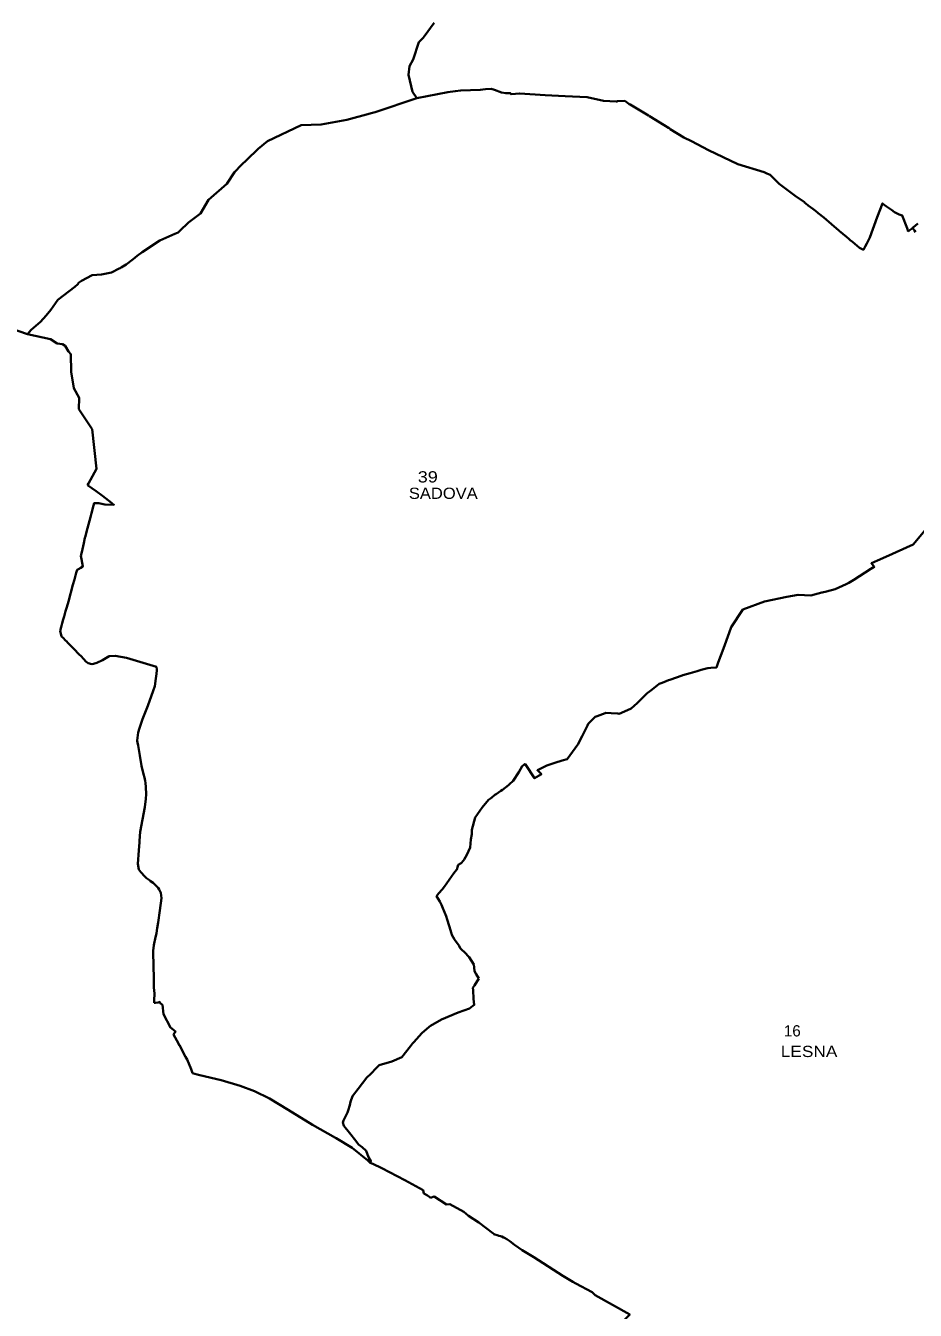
# Model space of a CAD drawing. Extents: x -610940 to -588976, y -1170376 to -1149800.
# Drawn here: x -598311 to -596331, y -1157762 to -1154902 of the extents above; entities that cross this region are included whole.
import ezdxf

# ---------------------------------------------------------------- set-up
doc = ezdxf.new("R2010")
doc.units = 0
doc.header["$LTSCALE"] = 10
doc.layers.add('54', color=7, linetype='Continuous', lineweight=35)
doc.layers.add('55', color=7, linetype='Continuous')
doc.layers.add('56', color=7, linetype='Continuous')

msp = doc.modelspace()

# ---------------------------------------------------------------- linework, layer by layer
at = {"layer": '54'}
for p, q in [((-597440.72, -1155063.97), (-597371.53, -1155050.6)), ((-598171.36, -1155921.75), (-598173.66, -1155924.96)), ((-598173.66, -1155924.96), (-598154.78, -1155938.64)), ((-598179.32, -1156041.24), (-598179.57, -1156042.23)), ((-598190.16, -1156110.24), (-598192.56, -1156111.77)), ((-598228.25, -1156265.11), (-598227.41, -1156265.97)), ((-598223.4, -1156270.12), (-598227.41, -1156265.97)), ((-598020.33, -1156345.49), (-598019.46, -1156337.07)), ((-598019.28, -1156335.32), (-598019.46, -1156337.07)), ((-598027.48, -1156383.15), (-598039.51, -1156416.77)), ((-598023.68, -1156372.54), (-598027.48, -1156383.15)), ((-598048.8, -1156568.82), (-598047.23, -1156576.36)), ((-598058.11, -1156720), (-598059.82, -1156738.65)), ((-598042.46, -1156799.86), (-598035.88, -1156804.79)), ((-598016.38, -1156821.88), (-598014.41, -1156825.37)), ((-598010.28, -1156832.71), (-598014.41, -1156825.37)), ((-598026.34, -1157039.35), (-598026.19, -1157024.28)), ((-598026.34, -1157039.35), (-598025.99, -1157043.8)), ((-598026.16, -1157021.34), (-598026.19, -1157024.28)), ((-598024.97, -1157056.82), (-598025.99, -1157043.8)), ((-598025.16, -1157077.69), (-598025.12, -1157072.76)), ((-598024.97, -1157056.82), (-598025.12, -1157072.76)), ((-597955.88, -1157197.66), (-597952.02, -1157204.06)), ((-597423.33, -1157502.84), (-597417.19, -1157506.85)), ((-597411.69, -1157510.45), (-597417.19, -1157506.85)), ((-597411.69, -1157510.45), (-597410.12, -1157511.52)), ((-597086.81, -1157702.7), (-597050.48, -1157721.63))]:
    msp.add_line(p, q, dxfattribs=at)
for points in [[(-597401.83, -1154896.17), (-597424.1, -1154926.78), (-597426.89, -1154929.69), (-597436.01, -1154939.33), (-597449.07, -1154977.53), (-597456.93, -1154992.27), (-597459.41, -1155011.97), (-597450.5, -1155049.32), (-597440.72, -1155063.97), (-597533.72, -1155095.04), (-597542.11, -1155097.33), (-597544.35, -1155097.94), (-597596.39, -1155112.14), (-597653.4, -1155122.02), (-597698.51, -1155123.98), (-597773.13, -1155159.09), (-597794.22, -1155176.34), (-597819.24, -1155201.09), (-597830.73, -1155212.47), (-597846.64, -1155228.22), (-597863.65, -1155254.11), (-597904.42, -1155289.69), (-597922.1, -1155320.54), (-597949.06, -1155340.26), (-597968.47, -1155359.05), (-597971.99, -1155362.46), (-597979.59, -1155365.94), (-598012.46, -1155380.94), (-598052.04, -1155406.28)], [(-597371.53, -1155050.6), (-597355.16, -1155048.25), (-597343, -1155046.39), (-597299.36, -1155045.19), (-597287.82, -1155043.79), (-597275.51, -1155043.07), (-597268.03, -1155045.06), (-597252.48, -1155051.2), (-597242.66, -1155052.79), (-597232.7, -1155052.31), (-597230.76, -1155055.09), (-597211.43, -1155053.08), (-597155.04, -1155056.88), (-597110.81, -1155059.06), (-597061.76, -1155061.63), (-597025, -1155069.9), (-596996.7, -1155070.91), (-596995.41, -1155071.14), (-596993.78, -1155070.7), (-596977.72, -1155069.87), (-596974.52, -1155072.14), (-596972.81, -1155073.32), (-596967.74, -1155076.82), (-596965.66, -1155078.18), (-596924.69, -1155102.41), (-596922.75, -1155103.5), (-596890.24, -1155123.8), (-596880.65, -1155129.85), (-596880.53, -1155129.92), (-596877.58, -1155131.63), (-596876.69, -1155132.47), (-596845.95, -1155151.29), (-596829.5, -1155159.19), (-596791.52, -1155179.38), (-596726.34, -1155210.29), (-596667.74, -1155228.2), (-596661.6, -1155231.25), (-596654.44, -1155234.55), (-596648.89, -1155239.88), (-596635.64, -1155252.59)], [(-596635.64, -1155252.59), (-596633.78, -1155254.38), (-596598.54, -1155281.19), (-596577.84, -1155295.58), (-596576.96, -1155296.39), (-596574.65, -1155298.2), (-596569.2, -1155302.4), (-596559.11, -1155310.21), (-596553.38, -1155314.69), (-596547.66, -1155319.16), (-596547.18, -1155319.44), (-596534.84, -1155329.64), (-596517.8, -1155344.17), (-596501.51, -1155358.2), (-596500.75, -1155358.65), (-596500.5, -1155358.86), (-596484.51, -1155372.16), (-596482.84, -1155373.55), (-596480.59, -1155375.44), (-596475.66, -1155379.52), (-596470.94, -1155383.42), (-596455.05, -1155396.67), (-596453.53, -1155397.4), (-596446.56, -1155401.32), (-596445.5, -1155399.55), (-596442.76, -1155394.21), (-596439, -1155387), (-596432.41, -1155374), (-596415.6, -1155329), (-596404.13, -1155298.13), (-596403.45, -1155298.8), (-596394.92, -1155304.89), (-596384.38, -1155312.42), (-596377.66, -1155317.21), (-596373.24, -1155319.56), (-596367.2, -1155322.78), (-596360.28, -1155324.79), (-596359.96, -1155324.81), (-596349.45, -1155353.2), (-596346.92, -1155360.69)], [(-596346.92, -1155360.69), (-596344.38, -1155358.64), (-596338.26, -1155353.56), (-596336.97, -1155352.54)], [(-596330.74, -1155362.38), (-596333.08, -1155358.65), (-596336.97, -1155352.54), (-596331.48, -1155348), (-596325.07, -1155342.61)], [(-598052.04, -1155406.28), (-598063.29, -1155415.08), (-598072.17, -1155422.02), (-598087.86, -1155434.12), (-598099.2, -1155440.77), (-598100.98, -1155441.82), (-598103.12, -1155442.89), (-598120.21, -1155451.46), (-598142.79, -1155456.28), (-598163.45, -1155457.83), (-598187.27, -1155470.14), (-598193.5, -1155475.15), (-598193.56, -1155475.24), (-598195.64, -1155477.47), (-598201.69, -1155483.93), (-598240.02, -1155512.71), (-598255.13, -1155535.26), (-598265.83, -1155547.67), (-598278.75, -1155561.42), (-598299.25, -1155579.49), (-598307.63, -1155589.43)], [(-598346.06, -1155575.76), (-598307.63, -1155589.43), (-598255.8, -1155600.47), (-598241.68, -1155609.85), (-598229.1, -1155611.46), (-598223.83, -1155614.73), (-598215.93, -1155627.71), (-598211.26, -1155633.56), (-598210.38, -1155673.12), (-598203.86, -1155709.15), (-598192.44, -1155731.13)], [(-598192.44, -1155731.13), (-598193.08, -1155755.78), (-598163.43, -1155800.82), (-598153.75, -1155888.66), (-598171.36, -1155921.75)], [(-598154.78, -1155938.64), (-598140.38, -1155949.07), (-598120.71, -1155964.6), (-598119.09, -1155966), (-598114.93, -1155968.65), (-598135.32, -1155967.99), (-598145.58, -1155966.04), (-598148.61, -1155965.14), (-598153.86, -1155965.31)], [(-598160.25, -1155970.16), (-598165.02, -1155987.9), (-598167.34, -1155996.67), (-598169.44, -1156004.5), (-598173.83, -1156020.65), (-598179.32, -1156041.24)], [(-598153.86, -1155965.31), (-598158.99, -1155965.49), (-598160.25, -1155970.16)], [(-598179.57, -1156042.23), (-598181.95, -1156054.13), (-598186.28, -1156074.1)], [(-596415.21, -1156093.02), (-596396.32, -1156084.7), (-596335.77, -1156057.31), (-596305.22, -1156020.75)], [(-598186.28, -1156074.1), (-598188.43, -1156082.66), (-598187.26, -1156089.83), (-598183.9, -1156106.22), (-598190.16, -1156110.24)], [(-596950.46, -1156410.4), (-596938.52, -1156398.81), (-596928.04, -1156388.44), (-596925.49, -1156386.61), (-596917.16, -1156380.09), (-596901.31, -1156367.29), (-596896.86, -1156365.73), (-596891.19, -1156363.6), (-596880.61, -1156359.54), (-596877.14, -1156358.35), (-596849.89, -1156348.58), (-596848.2, -1156348.06), (-596832.54, -1156343.54), (-596816.91, -1156339), (-596807.92, -1156336.39), (-596798.86, -1156333.76), (-596796.36, -1156333.04), (-596792.67, -1156332.73), (-596785.83, -1156332.15), (-596773.77, -1156331.21), (-596769.84, -1156320.22), (-596757.96, -1156288.9), (-596745.28, -1156253.69), (-596740.74, -1156241.51), (-596714.84, -1156202.02), (-596666.57, -1156184.54), (-596616.8, -1156173.93), (-596591.81, -1156169.19), (-596563.45, -1156170.48), (-596539.47, -1156164.49), (-596538.7, -1156164.25), (-596528.49, -1156161.94), (-596509.13, -1156156.55), (-596484.81, -1156145.45), (-596478.8, -1156142.64), (-596467.9, -1156135.71), (-596429.83, -1156111.83), (-596422.56, -1156107.09), (-596428.66, -1156099.2), (-596415.21, -1156093.02)], [(-598192.56, -1156111.77), (-598196.92, -1156113.79), (-598198.79, -1156120.45), (-598202.79, -1156135.01), (-598206.19, -1156147.3), (-598216.41, -1156184.02), (-598220.09, -1156196.98), (-598222.56, -1156205.75), (-598225.87, -1156217.33), (-598227.76, -1156224.46), (-598230.02, -1156232.65)], [(-598234.63, -1156249.78), (-598232.3, -1156241.1), (-598230.02, -1156232.65)], [(-598234.63, -1156249.78), (-598231.47, -1156261.87), (-598228.25, -1156265.11)], [(-598218.91, -1156274.75), (-598219.3, -1156274.35), (-598223.4, -1156270.12)], [(-598218.91, -1156274.75), (-598211.71, -1156282.33), (-598202.95, -1156291.42), (-598193.67, -1156300.39), (-598191.41, -1156302.61), (-598188.68, -1156305.13), (-598181.68, -1156312.39), (-598177.73, -1156317.44), (-598172.35, -1156321.14)], [(-598172.35, -1156321.14), (-598164.33, -1156323.36), (-598160.59, -1156322.63), (-598152.84, -1156320.48), (-598140.48, -1156315.01), (-598125.93, -1156306.08), (-598112.07, -1156305.23), (-598087.16, -1156309.75), (-598020.4, -1156329.99), (-598019.28, -1156335.32)], [(-598020.33, -1156345.49), (-598021.5, -1156355.86), (-598023.68, -1156372.54)], [(-598039.51, -1156416.77), (-598051.66, -1156446.09), (-598057.92, -1156465.85), (-598060.66, -1156475.91), (-598062.9, -1156493.59), (-598062.88, -1156495.37), (-598062.75, -1156497.36), (-598062.73, -1156498.29), (-598060.73, -1156504.95), (-598057.55, -1156526.95), (-598053.38, -1156550.03), (-598048.8, -1156568.82)], [(-597311.02, -1156665.4), (-597295.53, -1156642.5), (-597281.22, -1156625.98), (-597277.03, -1156622.5), (-597274.05, -1156620.2), (-597266.85, -1156614.77), (-597264.2, -1156612.97), (-597253.41, -1156605.59), (-597250.09, -1156603.17), (-597243.43, -1156598.3), (-597236.25, -1156593.1), (-597234.23, -1156590.48), (-597226.28, -1156583.13), (-597213.8, -1156563.87), (-597206.02, -1156550.78), (-597199.82, -1156545.58), (-597198.48, -1156547.37), (-597178.69, -1156577.68), (-597163.37, -1156568.59), (-597172.27, -1156559.84), (-597151.52, -1156549.5), (-597133.23, -1156543.68), (-597116.88, -1156538.52), (-597106.24, -1156535.07), (-597081.99, -1156502.85), (-597072.82, -1156484.31), (-597066.24, -1156470.93), (-597061.06, -1156460.37), (-597059.21, -1156456.68), (-597051.11, -1156448.57), (-597043.69, -1156441.16), (-597039.43, -1156439.62), (-597021.67, -1156433.01), (-597020.09, -1156432.39), (-597008.17, -1156433.06), (-596993.29, -1156433.87), (-596990.49, -1156433.96), (-596978.67, -1156429.13), (-596963.23, -1156422.69), (-596950.46, -1156410.4)], [(-598044.8, -1156587.68), (-598043.72, -1156597.22), (-598042.83, -1156613.03), (-598043.6, -1156623.29), (-598045.96, -1156641.72), (-598051.57, -1156669.64), (-598056.28, -1156696.93), (-598058.01, -1156717.13), (-598058.11, -1156720)], [(-598047.23, -1156576.36), (-598045.24, -1156583.54), (-598044.8, -1156587.68)], [(-597302.79, -1157023.53), (-597308.88, -1157013.74), (-597309.54, -1157012.92), (-597312.2, -1157006.69), (-597314.07, -1156992.58), (-597324.48, -1156975.83), (-597327.74, -1156972.29), (-597331.17, -1156968.38), (-597344.13, -1156956.18), (-597346.6, -1156950.83), (-597356.55, -1156936.27), (-597362.5, -1156926.59), (-597363.43, -1156923.54), (-597368.79, -1156906.07), (-597373.1, -1156892.2), (-597375.73, -1156884.91), (-597382.44, -1156866.95), (-597385.39, -1156859.5), (-597389.55, -1156852.36), (-597396.58, -1156840.22), (-597391.34, -1156833.44), (-597384.25, -1156825.08), (-597379.06, -1156818.63), (-597358.08, -1156789.23), (-597355.49, -1156785.49), (-597355.32, -1156785.24), (-597352.02, -1156781.53), (-597351.82, -1156781.3), (-597350.29, -1156775.28), (-597348.91, -1156770.53), (-597348.59, -1156770.35), (-597341.7, -1156766.38), (-597336.51, -1156760.44), (-597335.33, -1156758.86), (-597329.07, -1156748.15), (-597322.26, -1156732.16), (-597320.34, -1156713.9), (-597318.55, -1156702.04), (-597318.1, -1156692.44), (-597311.02, -1156665.4)], [(-598059.82, -1156738.65), (-598061.89, -1156768.06), (-598059.45, -1156781.06), (-598055.05, -1156786.59)], [(-598055.05, -1156786.59), (-598046.52, -1156796.73), (-598042.46, -1156799.86)], [(-598035.88, -1156804.79), (-598033.23, -1156806.59), (-598027.67, -1156810.79)], [(-598027.67, -1156810.79), (-598025.78, -1156812.16), (-598016.38, -1156821.88)], [(-598010.28, -1156832.71), (-598009.23, -1156844.81), (-598012.79, -1156871.78), (-598016.53, -1156898.78), (-598018.68, -1156911.18), (-598020.08, -1156922.81), (-598023.02, -1156935.03), (-598025.57, -1156945.43), (-598026.1, -1156948.87)], [(-598026.1, -1156948.87), (-598027.82, -1156961.98), (-598026.96, -1156998.47), (-598026.14, -1157019.41), (-598026.16, -1157021.34)], [(-597544.31, -1157433.57), (-597542.96, -1157430.01), (-597548.07, -1157421.21), (-597553.76, -1157407.04), (-597562.3, -1157398.54), (-597570.75, -1157392.99), (-597576.34, -1157384.93), (-597590.69, -1157366.7), (-597602.93, -1157351.19), (-597605.17, -1157343.85), (-597604.15, -1157339.57), (-597595.06, -1157321.64), (-597593.82, -1157316.93), (-597590.08, -1157305.41), (-597588.1, -1157298.06), (-597584.08, -1157285.18), (-597571.52, -1157269.08), (-597551.93, -1157244.09), (-597544.12, -1157236.18), (-597529.96, -1157221.82), (-597524.23, -1157216.22), (-597496.46, -1157207.92), (-597473.74, -1157198.26), (-597454.86, -1157173.89), (-597449.96, -1157168.2), (-597447.21, -1157165), (-597429.35, -1157145.45), (-597413.22, -1157131.26), (-597410.41, -1157129.08), (-597385.53, -1157114.91), (-597348.55, -1157098.99), (-597323.58, -1157090.53), (-597315.74, -1157084.16), (-597312.68, -1157082.11), (-597314.56, -1157068.57), (-597315.45, -1157049.55), (-597315.67, -1157044.4), (-597314.2, -1157041.88), (-597312.61, -1157039.31), (-597302.79, -1157023.53)], [(-598025.16, -1157077.69), (-598022.3, -1157077.53), (-598016.22, -1157076.84), (-598012.91, -1157075.5), (-598012.34, -1157078.44)], [(-598012.34, -1157078.44), (-598007.15, -1157082.25), (-598004.4, -1157102.89), (-597989.03, -1157132.58), (-597978.6, -1157140.5)], [(-597978.6, -1157140.5), (-597977.93, -1157142.48), (-597982.59, -1157147.71)], [(-597982.59, -1157147.71), (-597981.41, -1157149.58), (-597971.8, -1157166.33), (-597970.05, -1157172.17), (-597968.89, -1157171.86), (-597955.88, -1157197.66)], [(-597952.02, -1157204.06), (-597943.33, -1157224.97), (-597941.62, -1157229.71), (-597940.14, -1157234)], [(-597940.14, -1157234), (-597939.81, -1157233.97), (-597930, -1157237.04), (-597923.93, -1157238.49), (-597876.14, -1157249.73), (-597833.8, -1157262.31), (-597802.36, -1157274.07), (-597768.36, -1157290.34), (-597726.91, -1157315.61), (-597673.25, -1157349.23), (-597621.41, -1157378.35), (-597620.5, -1157378.86), (-597584.85, -1157400.05), (-597549.68, -1157428.4), (-597544.31, -1157433.57), (-597538.61, -1157436.24), (-597518.78, -1157445.34), (-597467.36, -1157472.46), (-597426.75, -1157494.43), (-597424.75, -1157501.96), (-597423.33, -1157502.84)], [(-597410.12, -1157511.52), (-597401.98, -1157509.06), (-597374.31, -1157526.39), (-597367.02, -1157525.65), (-597335.88, -1157542.94), (-597325.82, -1157551.54), (-597302.94, -1157566.36), (-597271.76, -1157590.33), (-597269.54, -1157592.06), (-597269.01, -1157592.49), (-597259.42, -1157595.67), (-597258.17, -1157596.01), (-597254.67, -1157596.93), (-597251.19, -1157597.82), (-597247.59, -1157599.84), (-597245.4, -1157601.05), (-597240.32, -1157603.81)], [(-597223.03, -1157616.59), (-597234, -1157608.48), (-597240.32, -1157603.81)], [(-597223.03, -1157616.59), (-597206.3, -1157628.35), (-597180, -1157644.04), (-597115.95, -1157685.32)], [(-597086.81, -1157702.7), (-597093.51, -1157698.7), (-597115.95, -1157685.32)], [(-597049.2, -1157723.15), (-597049.51, -1157722.78), (-597050.48, -1157721.63)], [(-597049.2, -1157723.15), (-597044.46, -1157727.97), (-597043.91, -1157728.55), (-596966.85, -1157771.12), (-596978.3, -1157783.32), (-596981.07, -1157786.27), (-596991, -1157796.97)]]:
    msp.add_lwpolyline(points, dxfattribs=at)

# ---------------------------------------------------------------- texts
at = {"layer": '55'}
for s, width, p in [('SADOVA ', 1.1, (-597458.41, -1155955.81)), ('LESNA ', 1.15, (-596630.5, -1157198.27))]:
    msp.add_text(s, height=25, dxfattribs=dict(at, width=width)).set_placement(p)
at = {"layer": '56', "width": 1.2}
msp.add_text('39 ', height=25, dxfattribs=at).set_placement((-597438.62, -1155919.21))
at = {"layer": '56'}
msp.add_text('16 ', height=25, dxfattribs=at).set_placement((-596623.34, -1157152.4))

doc.saveas('drawing.dxf')
